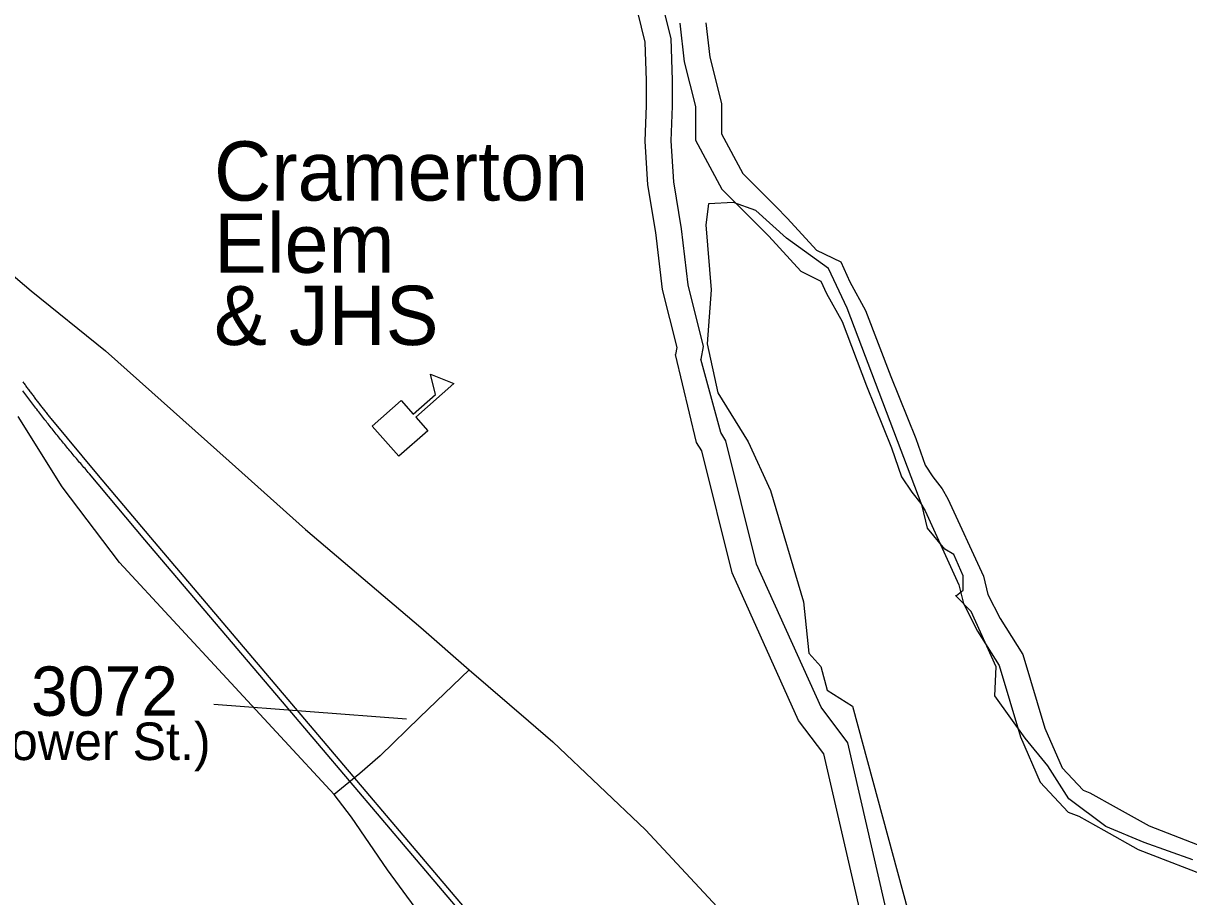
# Model space of a CAD drawing. Extents: x 1364363 to 1407445, y 538563 to 573342.
# Drawn here: x 1379352 to 1382303, y 547864 to 550075 of the extents above; entities that cross this region are included whole.
import ezdxf

# ---------------------------------------------------------------- set-up
doc = ezdxf.new("R2010")
doc.units = 0
for name, color, linetype in [('Exist Cultural Educational Facility High CELL', 7, 'Continuous'), ('Exist Cultural Educational Facility High Label', 7, 'Continuous'), ('Exist Hydrographic Buffer Line', 7, 'Continuous'), ('Exist Hydrographic Creek Double Shore', 7, 'Continuous'), ('Exist Hydrographic Island Shore', 7, 'Continuous'), ('Exist Railroad Mainline', 7, 'Continuous'), ('Exist Railroad Siding', 7, 'Continuous'), ('Exist Road Secondary Type 51 Attributed', 7, 'Continuous'), ('Exist Road Secondary Type 51 Label', 7, 'Continuous'), ('Exist Road Secondary Type 51 Number Label', 7, 'Continuous')]:
    doc.layers.add(name, color=color, linetype=linetype)

msp = doc.modelspace()

# ---------------------------------------------------------------- linework, layer by layer
at = {"layer": 'Exist Cultural Educational Facility High CELL'}
msp.add_lwpolyline([(1380236, 549055.3), (1380309.3, 549120.2), (1380339.8, 549085.8), (1380396, 549135.5), (1380383, 549186.8), (1380442.4, 549163.8), (1380346.2, 549078.6), (1380376.7, 549044.1), (1380303.4, 548979.2)], close=True, dxfattribs=at)
at = {"layer": 'Exist Hydrographic Buffer Line'}
for points in [[(1380954.4, 550188.6), (1380991.9, 550036.7), (1380995.5, 549931.7), (1380995.5, 549865.8), (1380992.2, 549777.5), (1380998.5, 549673.7), (1381018.3, 549555), (1381034.7, 549413.7), (1381073.8, 549257.1), (1381068.2, 549225.3)], [(1381014.4, 550075.5), (1381025.7, 549977.9), (1381054.8, 549864.4), (1381054.8, 549779.4), (1381120.7, 549655.9), (1381211.2, 549565.3), (1381240.2, 549536.2), (1381321.2, 549447.8), (1381372.1, 549422.9), (1381386.3, 549391.4), (1381425.5, 549320.9), (1381487.6, 549157.4), (1381550.8, 549000.9), (1381576.4, 548927.6), (1381602.4, 548888.6), (1381624.7, 548859.9), (1381635.6, 548841.4), (1381721.4, 548654.1), (1381732.7, 548606.6), (1381768.5, 548536.2), (1381823.5, 548449.9), (1381877.5, 548268.8), (1381927.1, 548154.4), (1381998.4, 548078.6), (1382024.9, 548068), (1382088, 548033.2), (1382175.4, 547984.3), (1382371.7, 547907.6)], [(1383249.8, 547141), (1383032.8, 547196.3), (1382665.7, 547215.8), (1382437.7, 547170.9), (1382359.8, 547107.8), (1382222.7, 547035.4), (1382194, 546956.3), (1382153.3, 546925.8), (1382125.5, 546918.9), (1382046.8, 546931), (1381968, 546970.2), (1381904.9, 547042.3), (1381735.4, 547159), (1381611, 547512.4), (1381440.1, 548253.9), (1381372.5, 548344.2), (1381209.2, 548705.8), (1381131.5, 549018.8), (1381118.6, 549039.5), (1381068.2, 549225.3)]]:
    msp.add_lwpolyline(points, dxfattribs=at)
at = {"layer": 'Exist Hydrographic Creek Double Shore'}
for points in [[(1380889.7, 550176.9), (1380926.5, 550027.7), (1380929.9, 549930.6), (1380929.9, 549867), (1380926.5, 549776.7), (1380933.2, 549666.3), (1380953.3, 549545.8), (1380970, 549401.9), (1381006.8, 549254.7), (1381003.6, 549236.6)], [(1381080.3, 550076.9), (1381090.4, 549989.8), (1381120.5, 549872.7), (1381120.5, 549795.8), (1381174, 549695.4), (1381257.6, 549611.7), (1381287.7, 549581.6), (1381361.2, 549501.3), (1381422.1, 549471.4), (1381445, 549420.9), (1381485.2, 549348.6), (1381548.7, 549181.3), (1381612.2, 549024), (1381635.6, 548957.1), (1381655.7, 548927), (1381679.1, 548896.9), (1381693.8, 548871.8), (1381783.8, 548675.5), (1381794.7, 548629.4), (1381825.6, 548568.8), (1381883.7, 548477.4), (1381939.3, 548291.4), (1381982.8, 548191), (1382036.3, 548134.1), (1382053, 548127.4), (1382119.9, 548090.6), (1382203.5, 548043.7), (1382400.8, 547966.8)], [(1383131.6, 547103.4), (1383022.9, 547131.1), (1382670.3, 547149.8), (1382466.3, 547109.7), (1382396.1, 547052.8), (1382275.7, 546989.2), (1382249, 546915.6), (1382182.1, 546865.4), (1382128.6, 546852), (1382026.7, 546867.7), (1381927.1, 546917.2), (1381860.9, 546993), (1381680.6, 547117.1), (1381547.9, 547494.1), (1381379.3, 548225.7), (1381315.6, 548310.6), (1381146.9, 548684.2), (1381070.3, 548992.9), (1381057.3, 549013.8), (1381003.6, 549236.6)], [(1383131.6, 547103.4), (1383022.9, 547131.1), (1382670.3, 547149.8), (1382466.3, 547109.7), (1382396.1, 547052.8), (1382275.7, 546989.2), (1382249, 546915.6), (1382182.1, 546865.4), (1382128.6, 546852), (1382026.7, 546867.7), (1381927.1, 546917.2), (1381860.9, 546993), (1381680.6, 547117.1), (1381547.9, 547494.1), (1381379.3, 548225.7), (1381315.6, 548310.6), (1381146.9, 548684.2), (1381070.3, 548992.9), (1381057.3, 549013.8), (1381003.6, 549236.6)]]:
    msp.add_lwpolyline(points, dxfattribs=at)
at = {"layer": 'Exist Hydrographic Island Shore'}
for points in [[(1381438.4, 549354.1), (1381391.5, 549454.5), (1381284.5, 549531.5), (1381207.6, 549601.8), (1381150.8, 549621.9), (1381087.2, 549618.5), (1381080.5, 549565), (1381093.9, 549401), (1381083.9, 549263.8), (1381110.6, 549140), (1381187.6, 549016.2), (1381244.4, 548892.3), (1381328, 548611.2), (1381341.4, 548480.7), (1381371.5, 548447.3), (1381388.2, 548387), (1381451.7, 548346.9), (1381782.9, 547126.2)], [(1382314.1, 547958.1), (1382190.4, 548001.6), (1382093.4, 548041.8), (1381999.8, 548112.1), (1381946.3, 548195.7), (1381889.4, 548266), (1381812.5, 548373.1), (1381815.9, 548446.7), (1381752.5, 548586.6), (1381712.4, 548626.7), (1381715.7, 548626.7), (1381732.4, 548640.1), (1381732.4, 548676.9), (1381709, 548730.5), (1381685.6, 548743.9), (1381642.1, 548797.4), (1381628.8, 548854.3), (1381438.4, 549354.1)]]:
    msp.add_lwpolyline(points, dxfattribs=at)
at = {"layer": 'Exist Railroad Mainline'}
for points in [[(1379519.7, 548935.3), (1379516.9, 548938.5), (1379514.1, 548941.7), (1379511.4, 548944.9), (1379508.6, 548948), (1379505.8, 548951.2), (1379503.2, 548954.4), (1379500.4, 548957.5), (1379497.6, 548960.8), (1379494.9, 548964), (1379492.1, 548967.2), (1379489.5, 548970.4), (1379486.8, 548973.6), (1379484, 548976.8), (1379481.2, 548980), (1379478.7, 548983.2), (1379475.9, 548986.5), (1379473.2, 548989.7), (1379470.5, 548992.9), (1379467.8, 548996.2), (1379465.1, 548999.4), (1379462.4, 549002.6), (1379459.8, 549005.9), (1379457.1, 549009.1), (1379454.4, 549012.4), (1379451.7, 549015.6), (1379449.1, 549018.9), (1379446.4, 549022.2), (1379443.7, 549025.4), (1379441.1, 549028.7), (1379438.5, 549032), (1379435.9, 549035.3), (1379433.2, 549038.5), (1379430.6, 549041.8), (1379428, 549045.1), (1379425.3, 549048.4), (1379422.8, 549051.7), (1379420.1, 549055), (1379417.5, 549058.3), (1379414.9, 549061.6), (1379412.2, 549064.9), (1379409.8, 549068.2), (1379407.1, 549071.5), (1379404.5, 549074.9), (1379402, 549078.2), (1379399.4, 549081.5), (1379396.7, 549084.8), (1379394.3, 549088.1), (1379391.6, 549091.5), (1379389.2, 549094.8), (1379386.5, 549098.2), (1379384, 549101.5), (1379381.5, 549104.9), (1379378.9, 549108.2), (1379376.3, 549111.5), (1379373.9, 549114.9), (1379371.4, 549118.3), (1379368.8, 549121.7), (1379366.3, 549125), (1379363.7, 549128.4), (1379361.3, 549131.7), (1379358.7, 549135.2), (1379356.2, 549138.6), (1379353.8, 549141.9), (1379351.2, 549145.3)], [(1381235.1, 546914.3), (1381070.9, 547103.6), (1380761.8, 547470), (1380338.5, 547968.9), (1380018.2, 548346.9), (1379659.7, 548768), (1379519.7, 548935.3)]]:
    msp.add_lwpolyline(points, dxfattribs=at)
at = {"layer": 'Exist Railroad Siding'}
for points in [[(1379351, 549167.8), (1379352.7, 549165.6), (1379354.3, 549163.4), (1379355.8, 549161.3), (1379357.5, 549159.1), (1379359.1, 549156.9), (1379360.8, 549154.7), (1379362.3, 549152.5), (1379363.8, 549150.3), (1379365.5, 549148.1), (1379367.1, 549145.9), (1379368.9, 549143.7), (1379370.5, 549141.6), (1379372.1, 549139.4), (1379373.8, 549137.3), (1379375.4, 549135.1), (1379377, 549132.9), (1379378.6, 549130.7), (1379380.2, 549128.6), (1379381.9, 549126.4), (1379383.6, 549124.2), (1379385.3, 549122), (1379386.9, 549119.9), (1379388.5, 549117.7), (1379390.3, 549115.6), (1379391.9, 549113.4), (1379393.5, 549111.2), (1379395.1, 549109.1), (1379396.8, 549106.9), (1379398.5, 549104.8), (1379400.2, 549102.7), (1379401.9, 549100.5), (1379403.5, 549098.4), (1379405.3, 549096.3), (1379406.9, 549094.1), (1379408.6, 549092), (1379410.3, 549089.8), (1379412, 549087.7), (1379413.7, 549085.5), (1379415.4, 549083.4), (1379417, 549081.3), (1379418.8, 549079.2), (1379420.3, 549077), (1379422.2, 549074.9)], [(1379422.2, 549074.9), (1379541.6, 548930.4), (1379683.9, 548762.6), (1379890.1, 548518.7), (1380600.1, 547681.6), (1381225.6, 546946.1)]]:
    msp.add_lwpolyline(points, dxfattribs=at)
at = {"layer": 'Exist Road Secondary Type 51 Attributed'}
for points in [[(1378382.3, 551904.1), (1378429.8, 551811.9), (1378473.8, 551674.2), (1378543.7, 551422.7), (1378610.7, 551208.7), (1378661.1, 551053.3), (1378707.4, 550913.3), (1378778.5, 550704.8), (1378942.4, 550194.7), (1378990.8, 550031.7), (1379059.7, 549823.2), (1379090, 549724.8), (1379170.9, 549598.9), (1379210.9, 549552.4), (1379252, 549499.8), (1379372.3, 549398.4), (1379560.7, 549245.9), (1379873.6, 548966.6), (1380066.5, 548794), (1380359.3, 548545.8), (1380481.3, 548439.1)], [(1380139.7, 548123.2), (1379595.8, 548710.8), (1379450.9, 548901.7), (1379339, 549080.1)], [(1380481.3, 548439.1), (1380356.1, 548318.8), (1380256, 548221), (1380204.6, 548176)], [(1380481.3, 548439.1), (1380631.8, 548309.8), (1380693, 548256.5), (1380928.1, 548033.7), (1381155, 547789.4), (1381234.9, 547704), (1381317.9, 547610.9), (1381393.8, 547531.4), (1381435.8, 547479.1), (1381471.8, 547426.7), (1381499.8, 547376.3), (1381517.8, 547325.8), (1381529.8, 547271.5), (1381521.8, 547203.7), (1381513.8, 547151.3), (1381498.8, 547114.4), (1381446.8, 547050.4), (1381388.4, 546986.7), (1381354.9, 546957.3)], [(1380204.6, 548176), (1380139.7, 548123.2)], [(1380636.6, 546348.8), (1380550.1, 546439.2), (1380489.6, 546523.5), (1380466.4, 546550.7), (1380449.4, 546583.9), (1380441.6, 546615.5), (1380440.7, 546654.4), (1380442.2, 546731.2), (1380458.9, 546831.9), (1380543.1, 547093.8), (1380547.2, 547138.4), (1380556.5, 547282.9), (1380555.3, 547392.7), (1380542.6, 547456.1), (1380523.6, 547532.1), (1380454, 547687.4), (1380274.7, 547932.1), (1380183.1, 548066), (1380139.7, 548123.2)]]:
    msp.add_lwpolyline(points, dxfattribs=at)
at = {"layer": 'Exist Road Secondary Type 51 Number Label'}
msp.add_line((1380322.7, 548313.8), (1379835.1, 548350.9), dxfattribs=at)

# ---------------------------------------------------------------- texts
at = {"layer": 'Exist Cultural Educational Facility High Label'}
for s, p in [('Cramerton', (1379835.3, 549626.6)), ('Elem', (1379835.3, 549443.8)), ('& JHS', (1379835.3, 549261))]:
    msp.add_text(s, height=150, dxfattribs=at).set_placement(p)
at = {"layer": 'Exist Road Secondary Type 51 Label'}
msp.add_text('(Mayflower St.)', height=95, dxfattribs=at).set_placement((1378972.5, 548210.3))
at = {"layer": 'Exist Road Secondary Type 51 Number Label'}
msp.add_text('3072', height=125, dxfattribs=at).set_placement((1379372, 548322.3))

doc.saveas('drawing.dxf')
